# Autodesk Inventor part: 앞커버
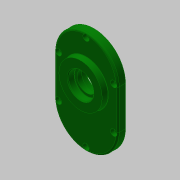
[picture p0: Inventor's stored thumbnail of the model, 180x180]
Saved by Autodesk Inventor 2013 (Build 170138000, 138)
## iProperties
Created: 2016-12
Part Number: 앞커버
Material: 알루미늄 6061
Document SubType Name: Modeling
Designer: mduedu
Density: 2.71 g/cm^3
Mass: 264.838 g
Surface Area: 264.105 cm^2
Volume: 97.726 cm^3
Author: mduedu
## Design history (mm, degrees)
sketch "스케치1"
  geometry: L1 (40, -25)-(40, 25); L2 (-40, 25)-(-40, -25); L3 (-40, -25)-(40, 25); L4 (40, -25)-(-40, 25); A1 r 40 centre (0, 25) between (40, 25) and (-40, 25); A2 r 40 centre (0, -25) between (-40, -25) and (40, -25); 1 further point
  constraints: 8 end point, 4 point on circle, 4 tangent, 2 centre point, 2 midpoint, 1 parallel, 1 vertical
  dimensions: "d0" = 130 dimension on A2 A1; "d2" = 80 distance between parallel lines of L1 L2
extrude "돌출1" new body sketch "스케치1" distance "d3" = 10; taper "d4" = 0 deg
sketch "스케치2"
  geometry: C1 r 21 at (0, 11); 1 further point
  constraints: 1 centre point, 1 vertical alignment
  dimensions: "d5" = 42 diameter of C1; "d7" = 11 distance of C1.centre point (0, 0)
extrude "돌출2" join sketch "스케치2" distance "d8" = 7; taper "d9" = 0 deg
sketch "스케치3"
  geometry: C1 r 15 at (0, -33.1); C2 r 21 at (0, 11) reference; 1 further point
  constraints: 1 centre point, 1 vertical alignment
  dimensions: "d10" = 30 diameter of C1; "d71" = 44.1 distance of C1.centre C2.centre
extrude "돌출3" join sketch "스케치3" distance "d12" = 7; taper "d13" = 0 deg
sketch "스케치4"
  geometry: C1 r 28 at (0, 11); A1 r 21 centre (0, 11) between (8.978, -7.984) and (-8.978, -7.984) reference; 1 further point
  constraints: 1 centre point, 1 coincident
  dimensions: "d14" = 56 diameter of C1
extrude "돌출4" join sketch "스케치4" distance "d15" = 7; taper "d16" = -5 deg
hole "구멍1" diameter "d19" = 35; stored, may be unused: countersink angle "d23" = 90 deg, drill point angle "d25" = 0 deg; dims "d17" = 10, "d18" = 10, "d20" = 6, "d21" = 4, "d22" = 2, "d24" = 10
hole "구멍2" diameter "d28" = 22; stored, may be unused: countersink angle "d32" = 90 deg, drill point angle "d34" = 0 deg; dims "d26" = 10, "d27" = 10, "d29" = 6, "d30" = 4, "d31" = 2, "d33" = 7
hole "구멍3" diameter "d37" = 19; stored, may be unused: countersink angle "d41" = 90 deg, drill point angle "d43" = 0 deg; dims "d35" = 10, "d36" = 10, "d38" = 6, "d39" = 4, "d40" = 2, "d42" = 1
hole "구멍4" diameter "d46" = 32; stored, may be unused: countersink angle "d50" = 90 deg, drill point angle "d52" = 0 deg; dims "d44" = 10, "d45" = 10, "d47" = 6, "d48" = 4, "d49" = 2, "d51" = 8
hole "구멍5" diameter "d55" = 25; stored, may be unused: countersink angle "d59" = 90 deg, drill point angle "d61" = 0 deg; dims "d53" = 10, "d54" = 10, "d56" = 6, "d57" = 4, "d58" = 2, "d60" = 8
fillet "모깎기1" dims "d62" = 0.3
fillet "모깎기2" dims "d63" = 2
chamfer "모따기1" distance "d64" = 1; stored, may be unused: second distance "d65" = 2, angle "d66" = 45 deg
fillet "모깎기4" dims "d68" = 2
fillet "모깎기5" dims "d69" = 0.3
fillet "모깎기6" dims "d70" = 2
sketch "스케치5"
  geometry: L1 (-40, 25)-(-40, -25) reference; L2 (40, -25)-(40, 25) reference; L3 (35, 25)-(35, -25); L4 (-35, -25)-(-35, 25); A1 r 40 centre (0, 25) between (40, 25) and (-40, 25) reference; A2 r 40 centre (0, -25) between (-40, -25) and (40, -25) reference; A3 r 35 centre (0, 25) between (35, 25) and (-35, 25); A4 r 35 centre (0, -25) between (-35, -25) and (35, -25); 2 further points
  constraints: 5 point on circle, 4 end point, 2 centre point, 1 vertical alignment, 3 other
  dimensions: "d72" = 5 distance between parallel lines of L2 L3
sketch "스케치7"
  geometry: 1 further point
hole "구멍7" sketch "스케치7" at (0, 60) diameter "d80" = 4.5; stored, may be unused: countersink angle "d84" = 90 deg, drill point angle "d86" = 0 deg; dims "d81" = 6, "d82" = 8, "d83" = 4.6, "d85" = 8
node "솔리드1"
pattern_linear "직사각형 패턴1"
